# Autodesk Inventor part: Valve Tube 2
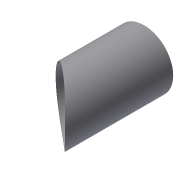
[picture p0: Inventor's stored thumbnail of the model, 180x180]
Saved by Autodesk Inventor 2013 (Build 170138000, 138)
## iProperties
Created: 2012-08
Part Number: Valve Tube 2
Document SubType Name: Modeling
Designer: dms52
Density: 1 g/cm^3
Material: Generic
Author: dms52
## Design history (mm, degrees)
sketch "Sketch1"
  geometry: C1 r 38.1 at (0, 0); C2 r 36.449 at (0, 0); 1 further point
  constraints: 2 centre point, 2 coincident
  dimensions: "d0" = 76.2 diameter of C1; "d1" = 1.651 radial gap between concentric circles of C1 C2
extrude "Extrusion1" new body sketch "Sketch1" distance "d2" = 203.2; taper "d3" = 0 deg
sketch "Sketch3"
  geometry: L1 (0, -349.804)-(0, 2098.826) reference; L2 (-38.1, 0)-(38.1, 0) reference; C1 r 476.25 at (304.8, 472.44); 1 further point
  constraints: 1 centre point
  dimensions: "d6" = 952.5 diameter of C1; "d7" = 472.44 distance from line of L2 C1.centre; "d8" = 304.8 distance from line of L1 C1.centre
extrude "Extrusion3" cut sketch "Sketch3" stored distance "d9" = 0; taper "d10" = 0 deg
body "Solid1"
